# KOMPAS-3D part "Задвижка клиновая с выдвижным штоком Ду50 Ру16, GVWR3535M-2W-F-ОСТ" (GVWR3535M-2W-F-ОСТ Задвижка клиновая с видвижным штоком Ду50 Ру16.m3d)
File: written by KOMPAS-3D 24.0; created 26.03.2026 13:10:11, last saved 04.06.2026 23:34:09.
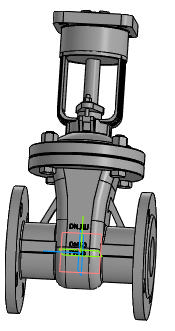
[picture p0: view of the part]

Document properties: Автор: R2D2; Полное имя файла: E:\Работа\Зайцев\GVWR3535M-2W-F-ОСТ Задвижка клиновая 30нж941нж DN.ru Ду50-200 Ру16\исходные данные\DN50\GVWR3535M-2W-F-ОСТ Задвижка клиновая с видвижным штоком Ду50 Ру16.m3d

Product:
- Component [detail]: AS 1110 - M12 x 45  | qty 4  | pos. 2  | Комментарий: Болты и винты   шестигранные точные   метрические ISO; Автор: R2D2; additional columns: Сталь, мягкая; source file: AS 1110 - M12 x 45 AS 1110 - M12 x 45.m3d
- Component [detail]: ANSI B18.2.4.2M - M12x1,75 - 18  | designation ANSI B18.2.4.2M - M12x1,75  | qty 4  | pos. 3  | Комментарий: Типы метрических   шестигранных гаек   2; Автор: R2D2; additional columns: Сталь, мягкая; source file: ANSI B18.2.4.2M - M12x1,75 ANSI B18.2.4.2M - M12x1,75 - 18.m3d
- Component [detail]: ANSI B18.2.4.2M - M5x0,8 - 8  | designation ANSI B18.2.4.2M - M5x0,8  | qty 1  | pos. 4  | Комментарий: Типы метрических   шестигранных гаек   2; Автор: R2D2; additional columns: Сталь, мягкая; source file: ANSI B18.2.4.2M - M5x0,8 ANSI B18.2.4.2M - M5x0,8 - 8.m3d
- Component [detail]: Деталь1  | qty 1  | pos. 5  | Автор: R2D2; additional columns: Типовые; source file: 2.m3d
- Component [detail]: Фланец  | qty 1  | pos. 5  | Автор: R2D2; additional columns: Типовые; source file: Фланец DN50 PN16 D160 b17.m3d
- Component [detail]: Фланец  | designation 01  | qty 1  | pos. 6  | Автор: R2D2; additional columns: Типовые; source file: Фланец DN50 PN16 D160 b17.m3d
- Component [detail]: ANSI B18.2.4.2M - M5x0,8 - 8  | designation ANSI B18.2.4.2M - M5x0,8-01  | qty 1  | pos. 7  | Комментарий: Типы метрических   шестигранных гаек   2; Автор: R2D2; additional columns: Сталь, мягкая; source file: ANSI B18.2.4.2M - M5x0,8 ANSI B18.2.4.2M - M5x0,8 - 8.m3d
- Component [assembly]: DN50_3D_STEP  | designation Сборка  | qty 1  | Масса: 2.725126; Автор: R2D2; source file: Фланец А.a3d
- Part/product: Задвижка клиновая с выдвижным штоком Ду50 Ру16  | designation GVWR3535M-2W-F-ОСТ
    Масса: 12
    Раздел спецификации: Прочие изделия
    Примечание: D040-08606

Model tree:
1. Массив по концентрической сетке:1  (labels: Грань.Твердое тело1)  (4 pattern instances)
     Шаг 2 = 360
2. Скругление:1  (with: Ребро.Операция без истории:2)
     Радиус = 5
3. Элемент выдавливания:1  (with: Грань.Элемент выдавливания:1, Грань.Операция без истории:2)
     Расстояние 1 = 48.9137
4. Элемент выдавливания:2  (with: Грань.Элемент выдавливания:1)
     Расстояние 1 = 70.4137
5. Элемент выдавливания:3  (with: Грань.Элемент выдавливания:1, Грань.Элемент вращения:1)
     Расстояние 1 = 13.6136
6. Элемент выдавливания:4  (with: Грань.Элемент выдавливания:1, Грань.Элемент вращения:1)
     Расстояние 1 = 11.9933
7. Скругление:2  (with: Ребро.Элемент выдавливания:3, Ребро.Элемент выдавливания:4)
     Радиус = 2
8. Эскиз:1
9. Элемент выдавливания:5  (with: Грань.Элемент выдавливания:1, Грань.Элемент вращения:1, Грань.Операция без истории:2)  (labels: Грань.Твердое тело1; Грань.Solid1; Solid1; Твердое тело1)
     Расстояние 1 = 46; Смещение 1 = 1; Расстояние = -90; Ориентация = 2; Ориентация = 2; Расстояние = -305

Referenced files in E:\Работа\Зайцев\GVWR3535M-2W-F-ОСТ Задвижка клиновая 30нж941нж DN.ru Ду50-200 Ру16\исходные данные\DN50\: AS 1110 - M12 x 45 AS 1110 - M12 x 45.m3d, ANSI B18.2.4.2M - M12x1,75 ANSI B18.2.4.2M - M12x1,75 - 18.m3d, ANSI B18.2.4.2M - M5x0,8 ANSI B18.2.4.2M - M5x0,8 - 8.m3d, 2.m3d, Фланец DN50 PN16 D160 b17.m3d, Фланец А.a3d
Referenced files in E:\Работа\Зайцев\GVWR3131M-2W-F-S Задвижка клиновая с выдвижным штоком DN.ru Ду50-200 Ру63\DN50\исходные материалы\: ANSI B18.2.4.2M - M12x1,75 ANSI B18.2.4.2M - M12x1,75 - 18.m3d, AS 1110 - M12 x 45 AS 1110 - M12 x 45.m3d
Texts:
  GVWR3535M-2W-F-ОСТ
  DN50
  GOST 26.020 Pr3
  PN16
  AS 1110 - M12 x 45 AS 1110 - M12 x 45 (1)
  ANSI B18.2.4.2M - M12x1,75 ANSI B18.2.4.2M - M12x1,75 - 18 (1)
  ANSI B18.2.4.2M - M5x0,8 ANSI B18.2.4.2M - M5x0,8 - 8
  Деталь1 Деталь1
  ANSI B18.2.4.2M - M12x1,75 ANSI B18.2.4.2M - M12x1,75 - 18 (2)
  AS 1110 - M12 x 45 AS 1110 - M12 x 45 (2)
  ANSI B18.2.4.2M - M12x1,75 ANSI B18.2.4.2M - M12x1,75 - 18 (3)
  AS 1110 - M12 x 45 AS 1110 - M12 x 45 (3)
  ANSI B18.2.4.2M - M12x1,75 ANSI B18.2.4.2M - M12x1,75 - 18 (4)
  AS 1110 - M12 x 45 AS 1110 - M12 x 45 (4)
  ANSI B18.2.4.2M - M5x0,8-01 ANSI B18.2.4.2M - M5x0,8 - 8
  Сборка DN50_3D_STEP
  Ось Y.Начало координат
  Ось Z.Начало координат
  Плоскость ZX.Начало координат
  Плоскость XY.Начало координат
  Плоскость ZY.Начало координат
